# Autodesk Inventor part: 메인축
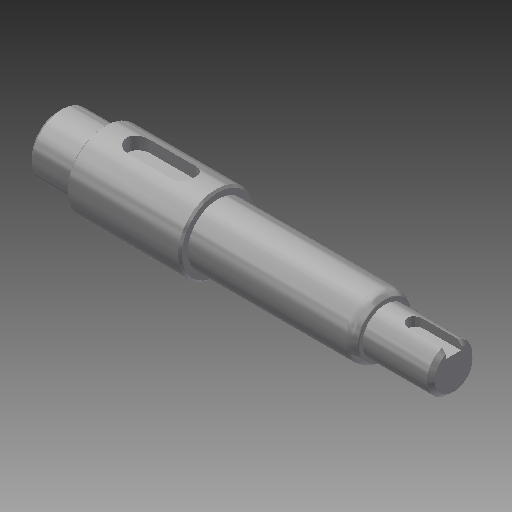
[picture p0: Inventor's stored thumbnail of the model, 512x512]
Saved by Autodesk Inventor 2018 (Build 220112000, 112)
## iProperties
Created: 2019-03
Part Number: 메인축
Material: 강철, 연강
Document SubType Name: Modeling
Designer: mduedu
Density: 1 g/cm^3
Appearance: 강철
Author: mduedu
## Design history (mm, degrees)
sketch "스케치1"
  geometry: L1 (0, 0)-(12, 0); L2 (12, 0)-(12, 8); L3 (12, 8)-(0, 8); L4 (0, 8)-(0, 0); L5 (12, 0)-(42, 0); L6 (42, 0)-(42, 10); L7 (42, 10)-(12, 10); L8 (12, 10)-(12, 0); L9 (42, 0)-(86, 0); L10 (86, 0)-(86, 8); L11 (86, 8)-(42, 8); L12 (42, 8)-(42, 0); L13 (86, 0)-(104, 0); L14 (104, 0)-(104, 6); L15 (104, 6)-(86, 6); L16 (86, 6)-(86, 0)
  constraints: 32 end point, 8 parallel, 4 horizontal, 4 perpendicular
  dimensions: "d0" = 16 diameter of L3 L1; "d2" = 20 diameter of L7 L5; "d3" = 16 diameter of L11 L9; "d4" = 12 diameter of L15 L13; "d5" = 12 distance of L2.end L3.end; "d6" = 30 distance of L6.end L7.end; "d7" = 86 distance between parallel lines of L10 L4; "d8" = 104 distance between parallel lines of L14 L4
revolve "회전1" sketch "스케치1" stored, may be unused: angle "d9" = 90 deg
node "작업 평면1"
sketch "스케치2" dims "d10" = 18
  geometry: L1 (6, -3)-(-6, -3); L2 (-6, -3)-(-6, 3); L3 (-6, 3)-(6, 3); L4 (6, 3)-(6, -3); L5 (15, 10)-(15, -10) reference; 3 further points
  constraints: 8 end point, 2 midpoint, 2 parallel, 2 vertical alignment, 1 horizontal, 1 horizontal alignment, 1 perpendicular, 4 other
  dimensions: "d12" = 6 distance between parallel lines of L3 L1; "d13" = 6 dimension on L5
extrude "돌출1" cut sketch "스케치2" distance "d14" = 3.5; taper "d15" = 0 deg
node "작업 평면2"
sketch "스케치3"
  geometry: L1 (-9, 6)-(-9, -6) reference; L2 (1, -2)-(-9, -2); L3 (1, 2)-(-9, 2); A1 r 2 centre (1, 0) between (1, -2) and (1, 2); 2 further points
  constraints: 4 end point, 2 point on circle, 2 point on line, 2 tangent, 1 centre point, 1 horizontal alignment, 1 midpoint, 1 parallel, 1 perpendicular
  dimensions: "d16" = 12 dimension on A1 L1; "d17" = 4 distance between parallel lines of L3 L2
extrude "돌출2" cut sketch "스케치3" distance "d18" = 2.5; taper "d19" = 0 deg
chamfer "모따기1" distance "d20" = 1; stored, may be unused: second distance "d21" = 2, angle "d22" = 45 deg
chamfer "모따기2" distance "d23" = 0.5; stored, may be unused: second distance "d24" = 2, angle "d25" = 45 deg
chamfer "모따기3" distance "d26" = 1.73; stored, may be unused: second distance "d27" = 2, angle "d28" = 30 deg
fillet "모깎기2" dims "d31" = 0.5, "d32" = 4
node "솔리드1"
